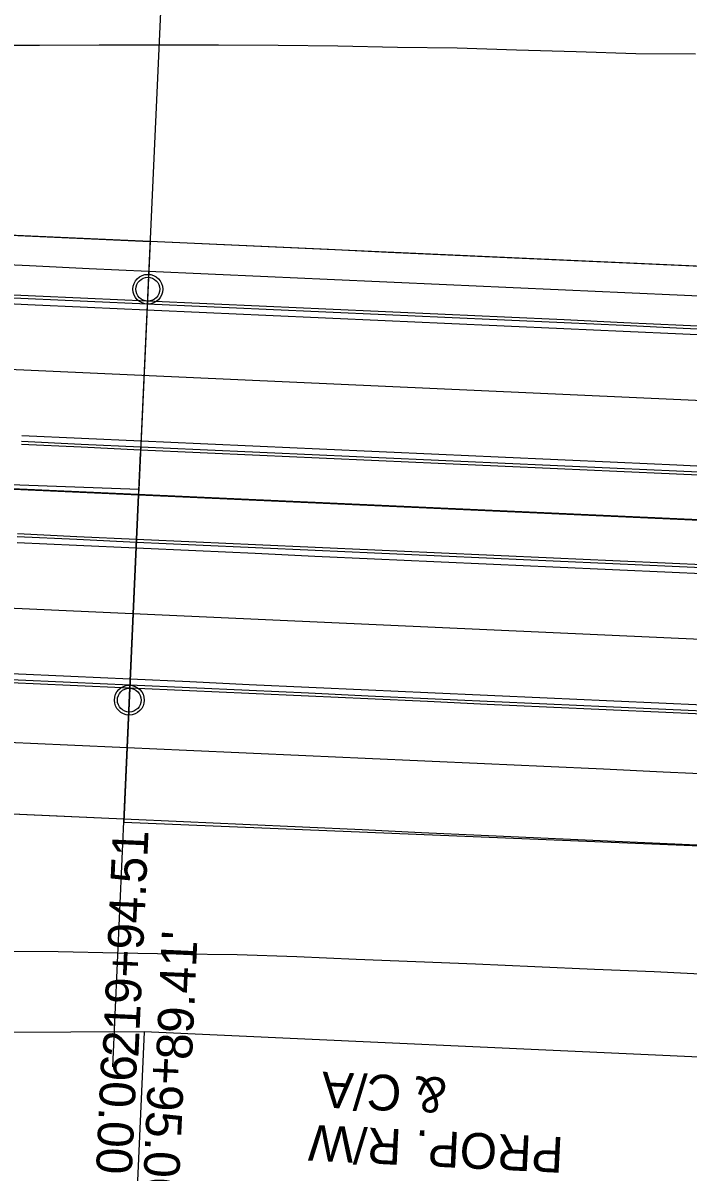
# Model space of a CAD drawing. Extents: x -70 to 701944, y -4 to 666871.
# Drawn here: x 666174.3 to 666285.8, y 656515 to 656708 of the extents above; entities that cross this region are included whole.
import ezdxf

# ---------------------------------------------------------------- set-up
doc = ezdxf.new("R2010")
doc.units = 0
for name, color, linetype in [('R_Detour', 7, 'Continuous'), ('R_Horz Alg', 7, 'Continuous'), ('R_No Plot', 7, 'Continuous'), ('R_Proposed Const Limits', 7, 'Continuous'), ('R_Proposed Road', 7, 'Continuous'), ('R_ROW', 7, 'Continuous'), ('R_Striping', 7, 'Continuous'), ('R_Temp Easement Annot', 7, 'Continuous'), ('R_Water', 7, 'Continuous')]:
    doc.layers.add(name, color=color, linetype=linetype)

msp = doc.modelspace()

# ---------------------------------------------------------------- linework, layer by layer
at = {"layer": 'R_Detour'}
for p in [(666198.78, 656742.54), (666189.31, 656532.83)]:
    msp.add_line(p, (666193.64, 656628.82), dxfattribs=at)
at = {"layer": 'R_Horz Alg'}
msp.add_line((667725.26, 656559.62), (664961.47, 656684.5), dxfattribs=at)
msp.add_lwpolyline([(666193.33, 656621.83), (666193.96, 656635.82)], dxfattribs=at)
at = {"layer": 'R_No Plot'}
for p, q in [((667813.84, 656555.62), (664810.54, 656691.32)), ((667725.26, 656559.62), (664961.47, 656684.5))]:
    msp.add_line(p, q, dxfattribs=at)
for points in [[(666043.56, 656630.46), (666045.78, 656679.6), (666095.66, 656675.85), (666195.56, 656671.28), (666193.68, 656629.72), (666093.74, 656633.34)], [(666345.41, 656664.51), (666195.56, 656671.28), (666193.64, 656628.82), (666343.49, 656622.05)], [(666043.26, 656630.44), (666093.74, 656633.34), (666193.64, 656628.82), (666191.18, 656574.38), (666092.19, 656578.79), (666041.19, 656577.87)], [(666193.64, 656628.82), (666191.16, 656573.88), (666311.08, 656568.96), (666330.05, 656566.97), (666340.91, 656564.86), (666343.49, 656622.05)]]:
    msp.add_lwpolyline(points, close=True, dxfattribs=at)
for centre in [(666195.2, 656663.29), (666192.09, 656594.36)]:
    msp.add_circle(centre, 2.5, dxfattribs=at)
at = {"layer": 'R_Proposed Const Limits'}
for points in [[(666287.07, 656702.72), (666277.07, 656702.79), (666267.07, 656703.12), (666257.07, 656703.39), (666247.08, 656703.71), (666237.07, 656703.87), (666227.07, 656704.09), (666217.07, 656704.19), (666207.06, 656704.26), (666197.05, 656704.23), (666187.04, 656704.22), (666177.03, 656704.2), (666167.02, 656704.18)], [(666290.1, 656548.26), (666280.12, 656548.79), (666270.13, 656549.18), (666260.14, 656549.62), (666250.15, 656550.06), (666240.15, 656550.47), (666230.16, 656550.87), (666220.17, 656551.3), (666210.18, 656551.65), (666200.17, 656551.75), (666190.17, 656551.9), (666180.17, 656552.13), (666170.16, 656552.21)]]:
    msp.add_lwpolyline(points, dxfattribs=at)
at = {"layer": 'R_Proposed Road'}
for points in [[(666295.46, 656666.77), (666285.47, 656667.22), (666275.48, 656667.67), (666265.49, 656668.12), (666255.5, 656668.57), (666245.51, 656669.02), (666235.52, 656669.47), (666225.53, 656669.93), (666215.54, 656670.38), (666205.55, 656670.83), (666195.56, 656671.28), (666185.57, 656671.73), (666175.58, 656672.18), (666165.59, 656672.63)], [(666295.23, 656661.77), (666285.24, 656662.22), (666275.25, 656662.67), (666265.26, 656663.13), (666255.27, 656663.58), (666245.28, 656664.03), (666235.29, 656664.48), (666225.3, 656664.93), (666215.31, 656665.38), (666205.32, 656665.83), (666195.33, 656666.28), (666185.35, 656666.74), (666175.36, 656667.19), (666165.37, 656667.64)], [(666294.98, 656656.28), (666284.99, 656656.73), (666275.01, 656657.18), (666265.02, 656657.63), (666255.03, 656658.08), (666245.04, 656658.53), (666235.05, 656658.98), (666225.06, 656659.44), (666215.07, 656659.89), (666205.08, 656660.34), (666195.09, 656660.79), (666185.1, 656661.24), (666175.11, 656661.69), (666165.12, 656662.14)], [(666295.01, 656656.78), (666285.02, 656657.23), (666275.03, 656657.68), (666265.04, 656658.13), (666255.05, 656658.58), (666245.06, 656659.03), (666235.07, 656659.48), (666225.08, 656659.94), (666215.09, 656660.39), (666205.1, 656660.84), (666195.11, 656661.29), (666185.12, 656661.74), (666175.13, 656662.19), (666165.14, 656662.64)], [(666294.94, 656655.28), (666284.95, 656655.73), (666274.96, 656656.18), (666264.97, 656656.63), (666254.98, 656657.08), (666244.99, 656657.53), (666235, 656657.99), (666225.01, 656658.44), (666215.02, 656658.89), (666205.03, 656659.34), (666195.04, 656659.79), (666185.05, 656660.24), (666175.06, 656660.69), (666165.07, 656661.15)], [(666403.83, 656628.34), (666393.84, 656628.79), (666383.85, 656629.24), (666373.87, 656629.69), (666363.88, 656630.14), (666353.89, 656630.59), (666343.9, 656631.04), (666333.91, 656631.49), (666323.92, 656631.95), (666313.93, 656632.4), (666303.94, 656632.85), (666293.95, 656633.3), (666283.96, 656633.75), (666273.97, 656634.2), (666263.98, 656634.65), (666253.99, 656635.11), (666244, 656635.56), (666234.01, 656636.01), (666224.02, 656636.46), (666214.03, 656636.91), (666204.04, 656637.36), (666194.05, 656637.81), (666184.06, 656638.26), (666174.07, 656638.72)], [(666293.95, 656633.3), (666283.96, 656633.75), (666273.97, 656634.2), (666263.98, 656634.65), (666253.99, 656635.11), (666244, 656635.56), (666234.01, 656636.01), (666224.02, 656636.46), (666214.03, 656636.91), (666204.04, 656637.36), (666194.05, 656637.81), (666184.06, 656638.26), (666174.07, 656638.72)], [(666403.77, 656626.84), (666393.78, 656627.29), (666383.79, 656627.74), (666373.8, 656628.19), (666363.81, 656628.64), (666353.82, 656629.09), (666343.83, 656629.54), (666333.84, 656630), (666323.85, 656630.45), (666313.86, 656630.9), (666303.87, 656631.35), (666293.88, 656631.8), (666283.89, 656632.25), (666273.9, 656632.7), (666263.91, 656633.16), (666253.92, 656633.61), (666243.93, 656634.06), (666233.94, 656634.51), (666223.95, 656634.96), (666213.96, 656635.41), (666203.97, 656635.86), (666193.98, 656636.32), (666183.99, 656636.77), (666174, 656637.22)], [(666293.88, 656631.8), (666283.89, 656632.25), (666273.9, 656632.7), (666263.91, 656633.16), (666253.92, 656633.61), (666243.93, 656634.06), (666233.94, 656634.51), (666223.95, 656634.96), (666213.96, 656635.41), (666203.97, 656635.86), (666193.98, 656636.32), (666183.99, 656636.77), (666174, 656637.22)], [(666403.79, 656627.34), (666393.8, 656627.79), (666383.81, 656628.24), (666373.82, 656628.69), (666363.83, 656629.14), (666353.84, 656629.59), (666343.85, 656630.04), (666333.86, 656630.5), (666323.87, 656630.95), (666313.88, 656631.4), (666303.89, 656631.85), (666293.9, 656632.3), (666283.91, 656632.75), (666273.92, 656633.2), (666263.93, 656633.66), (666253.94, 656634.11), (666243.95, 656634.56), (666233.96, 656635.01), (666223.97, 656635.46), (666213.98, 656635.91), (666203.99, 656636.36), (666194, 656636.81), (666184.01, 656637.27), (666174.02, 656637.72)], [(666293.9, 656632.3), (666283.91, 656632.75), (666273.92, 656633.2), (666263.93, 656633.66), (666253.94, 656634.11), (666243.95, 656634.56), (666233.96, 656635.01), (666223.97, 656635.46), (666213.98, 656635.91), (666203.99, 656636.36), (666194, 656636.81), (666184.01, 656637.27), (666174.02, 656637.72)], [(666403.07, 656611.35), (666393.08, 656611.8), (666383.09, 656612.26), (666373.1, 656612.71), (666363.11, 656613.16), (666353.12, 656613.61), (666343.13, 656614.06), (666333.14, 656614.51), (666323.15, 656614.96), (666313.16, 656615.41), (666303.17, 656615.87), (666293.18, 656616.32), (666283.19, 656616.77), (666273.2, 656617.22), (666263.21, 656617.67), (666253.22, 656618.12), (666243.23, 656618.57), (666233.24, 656619.03), (666223.25, 656619.48), (666213.26, 656619.93), (666203.27, 656620.38), (666193.28, 656620.83), (666183.29, 656621.28), (666173.3, 656621.73)], [(666293.18, 656616.32), (666283.19, 656616.77), (666273.2, 656617.22), (666263.21, 656617.67), (666253.22, 656618.12), (666243.23, 656618.57), (666233.24, 656619.03), (666223.25, 656619.48), (666213.26, 656619.93), (666203.27, 656620.38), (666193.28, 656620.83), (666183.29, 656621.28), (666173.3, 656621.73)], [(666403.09, 656611.85), (666393.1, 656612.3), (666383.11, 656612.75), (666373.12, 656613.21), (666363.13, 656613.66), (666353.14, 656614.11), (666343.15, 656614.56), (666333.16, 656615.01), (666323.17, 656615.46), (666313.18, 656615.91), (666303.19, 656616.37), (666293.2, 656616.82), (666283.21, 656617.27), (666273.22, 656617.72), (666263.23, 656618.17), (666253.24, 656618.62), (666243.25, 656619.07), (666233.26, 656619.52), (666223.27, 656619.98), (666213.28, 656620.43), (666203.29, 656620.88), (666193.3, 656621.33), (666183.31, 656621.78), (666173.32, 656622.23)], [(666293.2, 656616.82), (666283.21, 656617.27), (666273.22, 656617.72), (666263.23, 656618.17), (666253.24, 656618.62), (666243.25, 656619.07), (666233.26, 656619.52), (666223.27, 656619.98), (666213.28, 656620.43), (666203.29, 656620.88), (666193.3, 656621.33), (666183.31, 656621.78), (666173.32, 656622.23)], [(666403.02, 656610.35), (666393.03, 656610.8), (666383.04, 656611.26), (666373.05, 656611.71), (666363.06, 656612.16), (666353.07, 656612.61), (666343.08, 656613.06), (666333.09, 656613.51), (666323.1, 656613.96), (666313.11, 656614.42), (666303.12, 656614.87), (666293.13, 656615.32), (666283.14, 656615.77), (666273.15, 656616.22), (666263.16, 656616.67), (666253.17, 656617.12), (666243.19, 656617.58), (666233.2, 656618.03), (666223.21, 656618.48), (666213.22, 656618.93), (666203.23, 656619.38), (666193.24, 656619.83), (666183.25, 656620.28), (666173.26, 656620.73)], [(666293.13, 656615.32), (666283.14, 656615.77), (666273.15, 656616.22), (666263.16, 656616.67), (666253.17, 656617.12), (666243.19, 656617.58), (666233.2, 656618.03), (666223.21, 656618.48), (666213.22, 656618.93), (666203.23, 656619.38), (666193.24, 656619.83), (666183.25, 656620.28), (666173.26, 656620.73)], [(666292.1, 656592.34), (666282.11, 656592.79), (666272.12, 656593.24), (666262.13, 656593.7), (666252.14, 656594.15), (666242.15, 656594.6), (666232.16, 656595.05), (666222.17, 656595.5), (666212.18, 656595.95), (666202.19, 656596.4), (666192.2, 656596.86), (666182.21, 656597.31), (666172.22, 656597.76)], [(666292.14, 656593.34), (666282.15, 656593.79), (666272.16, 656594.24), (666262.17, 656594.69), (666252.18, 656595.15), (666242.19, 656595.6), (666232.2, 656596.05), (666222.21, 656596.5), (666212.22, 656596.95), (666202.23, 656597.4), (666192.24, 656597.85), (666182.25, 656598.31), (666172.26, 656598.76)], [(666292.07, 656591.84), (666282.08, 656592.29), (666272.09, 656592.75), (666262.1, 656593.2), (666252.11, 656593.65), (666242.12, 656594.1), (666232.13, 656594.55), (666222.14, 656595), (666212.16, 656595.45), (666202.17, 656595.9), (666192.18, 656596.36), (666182.19, 656596.81), (666172.2, 656597.26)], [(666310.97, 656580.98), (666301.61, 656581.4), (666291.62, 656581.85), (666281.63, 656582.3), (666271.64, 656582.76), (666261.65, 656583.21), (666251.66, 656583.66), (666241.67, 656584.11), (666231.68, 656584.56), (666221.69, 656585.01), (666211.7, 656585.46), (666201.71, 656585.91), (666191.72, 656586.37), (666181.73, 656586.82), (666171.74, 656587.27)], [(666310.97, 656580.98), (666301.61, 656581.4), (666291.62, 656581.85), (666281.63, 656582.3), (666271.64, 656582.76), (666261.65, 656583.21), (666251.66, 656583.66), (666241.67, 656584.11), (666231.68, 656584.56), (666221.69, 656585.01), (666211.7, 656585.46), (666201.71, 656585.91), (666191.72, 656586.37), (666181.73, 656586.82), (666171.74, 656587.27)], [(666291.62, 656581.85), (666281.63, 656582.3), (666271.64, 656582.76), (666261.65, 656583.21), (666251.66, 656583.66), (666241.67, 656584.11), (666231.68, 656584.56), (666221.69, 656585.01), (666211.7, 656585.46), (666201.71, 656585.91), (666191.72, 656586.37), (666181.73, 656586.82), (666171.74, 656587.27)], [(666291.08, 656569.86), (666281.09, 656570.32), (666271.1, 656570.77), (666261.11, 656571.22), (666251.12, 656571.67), (666241.13, 656572.12), (666231.14, 656572.57), (666221.15, 656573.02), (666211.16, 656573.48), (666201.17, 656573.93), (666191.18, 656574.38), (666181.19, 656574.83), (666171.2, 656575.28)]]:
    msp.add_lwpolyline(points, dxfattribs=at)
at = {"layer": 'R_ROW'}
msp.add_lwpolyline([(668068.22, 656367.07), (668015.2, 656409.61), (667518.06, 656430.84), (667204.93, 656412.96), (667078.78, 656456.7), (667035.95, 656483.66), (666996.35, 656493.45), (666927.34, 656472.55), (666845.47, 656477.25), (666774.58, 656503.47), (666573.01, 656517.59), (666494.28, 656503.13), (666386.7, 656514.99), (666322.44, 656532.91), (666194.58, 656538.69), (665874.18, 656537.15), (665794.4, 656521.73), (665682.43, 656524.79)], dxfattribs=at)
at = {"layer": 'R_Striping'}
for points in [[(666699.66, 656625.98), (666096.29, 656653.24), (665996.53, 656660.75), (665796.9, 656669.77)], [(666697.69, 656586.03), (666094.81, 656613.27), (665994.78, 656614.78), (665744.97, 656626.07)]]:
    msp.add_lwpolyline(points, dxfattribs=at)
at = {"layer": 'R_Temp Easement Annot'}
msp.add_lwpolyline([(666194.58, 656538.69), (666193, 656503.72)], dxfattribs=at)
at = {"layer": 'R_Water'}
for centre in [(666195.2, 656663.29), (666192.09, 656594.36)]:
    msp.add_circle(centre, 2, dxfattribs=at)

# ---------------------------------------------------------------- texts
at = {"layer": 'R_No Plot'}
for s, p in [('219+94.51 ', (666193.6, 656534.32)), ("89.41' ", (666202.59, 656533.91))]:
    msp.add_text(s, height=6, rotation=87.4131, dxfattribs=at).set_placement(p)
at = {"layer": 'R_ROW'}
for s, p in [('& C/A', (666245.45, 656531)), ('PROP. R/W ', (666265.06, 656521.03))]:
    msp.add_text(s, height=6, rotation=177.2014, dxfattribs=at).set_placement(p)
at = {"layer": 'R_Temp Easement Annot'}
for s, p in [('90.00', (666187.4, 656535.01)), ('+95.00', (666195.39, 656534.65))]:
    msp.add_text(s, height=6, rotation=267.4131, dxfattribs=at).set_placement(p)

doc.saveas('drawing.dxf')
